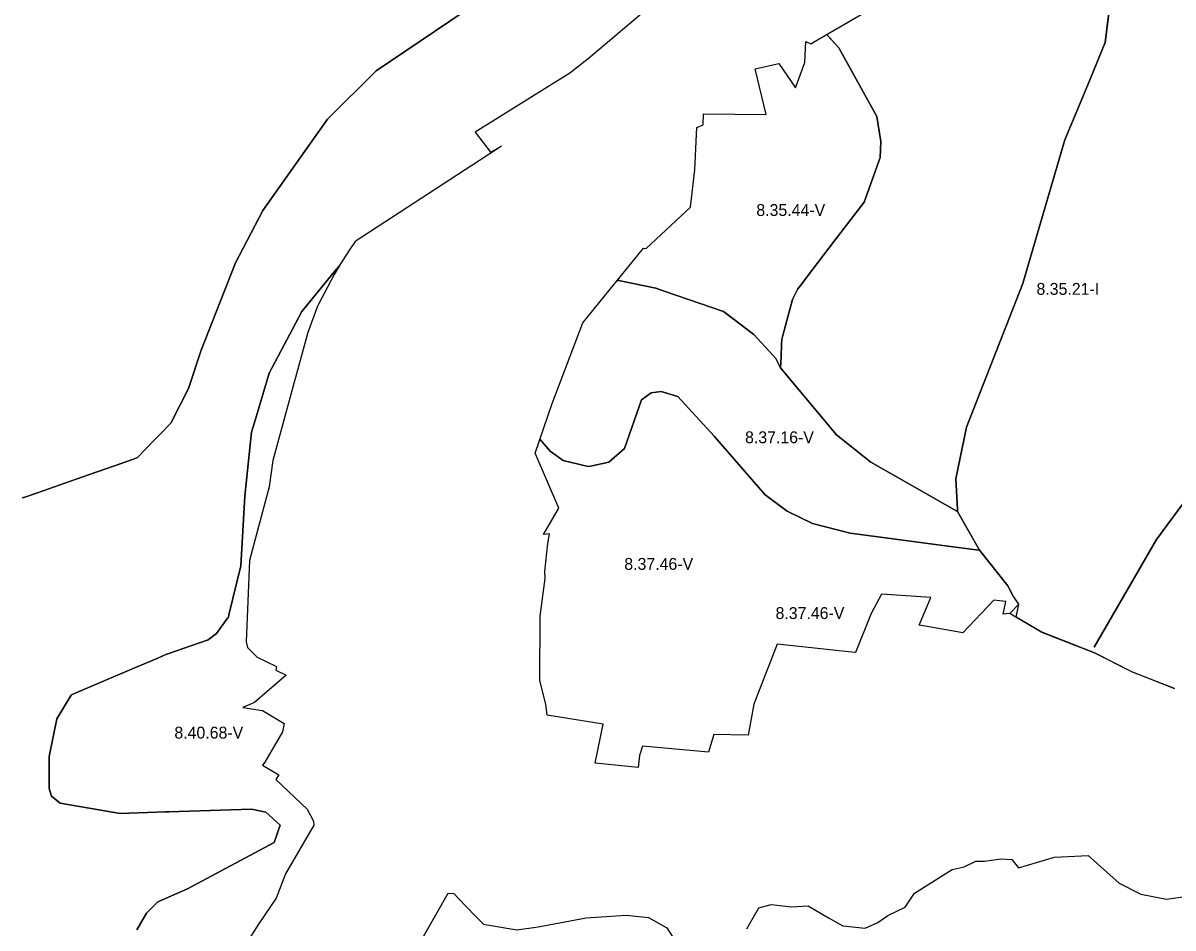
# Model space of a CAD drawing. Extents: x -547623 to -533936, y -1096714 to -1086523.
# Drawn here: x -543752 to -542784, y -1094794 to -1094032 of the extents above; entities that cross this region are included whole.
import ezdxf

# ---------------------------------------------------------------- set-up
doc = ezdxf.new("R2010")
doc.units = 0
doc.layers.add('Vrstva 27', color=7, linetype='Continuous')
doc.layers.add('Vrstva 28', color=7, linetype='Continuous')

msp = doc.modelspace()

# ---------------------------------------------------------------- linework, layer by layer
at = {"layer": 'Vrstva 28'}
for p, q in [((-542841, -1094048.5), (-542835.12, -1094000)), ((-542835.12, -1094000), (-542841, -1094048.5)), ((-543381, -1094022.5), (-543455, -1094072.5)), ((-543455, -1094072.5), (-543381, -1094022.5)), ((-543065.5, -1094053), (-543075.52, -1094041.89)), ((-543075.52, -1094041.89), (-543065.5, -1094053)), ((-542855.78, -1094084.15), (-542841, -1094048.5)), ((-542841, -1094048.5), (-542855.78, -1094084.15)), ((-543033.5, -1094111), (-543065.5, -1094053)), ((-543065.5, -1094053), (-543033.5, -1094111)), ((-543455, -1094072.5), (-543496, -1094113)), ((-543496, -1094113), (-543455, -1094072.5)), ((-542875, -1094130.5), (-542855.78, -1094084.15)), ((-542855.78, -1094084.15), (-542875, -1094130.5)), ((-543030, -1094132), (-543033.5, -1094111)), ((-543033.5, -1094111), (-543030, -1094132)), ((-543496, -1094113), (-543550.5, -1094190)), ((-543550.5, -1094190), (-543496, -1094113)), ((-543030.5, -1094145.5), (-543030, -1094132)), ((-543030, -1094132), (-543030.5, -1094145.5)), ((-542900.06, -1094215.92), (-542875, -1094130.5)), ((-542875, -1094130.5), (-542900.06, -1094215.92)), ((-543044, -1094183), (-543030.5, -1094145.5)), ((-543030.5, -1094145.5), (-543044, -1094183)), ((-543411.41, -1094176.18), (-543411.41, -1094176.18)), ((-543069.25, -1094215.92), (-543044, -1094183)), ((-543044, -1094183), (-543069.25, -1094215.92)), ((-543550.5, -1094190), (-543564.05, -1094215.92)), ((-543564.05, -1094215.92), (-543550.5, -1094190)), ((-543564.05, -1094215.92), (-543573.5, -1094234)), ((-543573.5, -1094234), (-543564.05, -1094215.92)), ((-543091.79, -1094245.3), (-543069.25, -1094215.92)), ((-543069.25, -1094215.92), (-543091.79, -1094245.3)), ((-542910.5, -1094251.5), (-542900.06, -1094215.92)), ((-542900.06, -1094215.92), (-542910.5, -1094251.5)), ((-543573.5, -1094234), (-543602.5, -1094307.5)), ((-543602.5, -1094307.5), (-543573.5, -1094234)), ((-543486.31, -1094236.92), (-543490.45, -1094243.92)), ((-543490.45, -1094243.92), (-543486.31, -1094236.92)), ((-543486.31, -1094236.92), (-543490, -1094241.5)), ((-543490, -1094241.5), (-543486.31, -1094236.92)), ((-543486.31, -1094236.92), (-543486.31, -1094236.92)), ((-543486.31, -1094236.92), (-543486.31, -1094236.92)), ((-543490, -1094241.5), (-543517.5, -1094275)), ((-543517.5, -1094275), (-543490, -1094241.5)), ((-543097.54, -1094252.8), (-543091.79, -1094245.3)), ((-543091.79, -1094245.3), (-543097.54, -1094252.8)), ((-543251, -1094249), (-543252, -1094248.95)), ((-543252, -1094248.95), (-543251, -1094249)), ((-543219.5, -1094255.5), (-543251, -1094249)), ((-543251, -1094249), (-543219.5, -1094255.5)), ((-543211.76, -1094258.15), (-543219.5, -1094255.5)), ((-543219.5, -1094255.5), (-543211.76, -1094258.15)), ((-543104.5, -1094265), (-543100, -1094256)), ((-543100, -1094256), (-543104.5, -1094265)), ((-543100, -1094256), (-543097.54, -1094252.8)), ((-543097.54, -1094252.8), (-543100, -1094256)), ((-542958, -1094372.5), (-542910.5, -1094251.5)), ((-542910.5, -1094251.5), (-542958, -1094372.5)), ((-543162.5, -1094275), (-543211.76, -1094258.15)), ((-543211.76, -1094258.15), (-543162.5, -1094275)), ((-543112.33, -1094294.16), (-543104.5, -1094265)), ((-543104.5, -1094265), (-543112.33, -1094294.16)), ((-543517.5, -1094275), (-543545, -1094327)), ((-543545, -1094327), (-543517.5, -1094275)), ((-543137, -1094294.5), (-543162.5, -1094275)), ((-543162.5, -1094275), (-543137, -1094294.5)), ((-543121.05, -1094311.74), (-543137, -1094294.5)), ((-543137, -1094294.5), (-543121.05, -1094311.74)), ((-543113.5, -1094298.5), (-543112.33, -1094294.16)), ((-543112.33, -1094294.16), (-543113.5, -1094298.5)), ((-543114.11, -1094313.07), (-543113.66, -1094302.45)), ((-543113.66, -1094302.45), (-543114.11, -1094313.07)), ((-543113.66, -1094302.45), (-543113.5, -1094298.5)), ((-543113.5, -1094298.5), (-543113.66, -1094302.45)), ((-543602.5, -1094307.5), (-543613, -1094340)), ((-543613, -1094340), (-543602.5, -1094307.5)), ((-543118.5, -1094314.5), (-543121.05, -1094311.74)), ((-543121.05, -1094311.74), (-543118.5, -1094314.5)), ((-543114.5, -1094322.5), (-543114.11, -1094313.07)), ((-543114.11, -1094313.07), (-543114.5, -1094322.5)), ((-543117.94, -1094315.62), (-543118.5, -1094314.5)), ((-543118.5, -1094314.5), (-543117.94, -1094315.62)), ((-543116.13, -1094319.23), (-543117.94, -1094315.62)), ((-543117.94, -1094315.62), (-543116.13, -1094319.23)), ((-543114.5, -1094322.5), (-543116.13, -1094319.23)), ((-543116.13, -1094319.23), (-543114.5, -1094322.5)), ((-543067.5, -1094379), (-543114.5, -1094322.5)), ((-543114.5, -1094322.5), (-543067.5, -1094379)), ((-543545, -1094327), (-543555.87, -1094362.88)), ((-543555.87, -1094362.88), (-543545, -1094327)), ((-543613, -1094340), (-543628, -1094369)), ((-543628, -1094369), (-543613, -1094340)), ((-543215, -1094342.5), (-543223.5, -1094343.5)), ((-543223.5, -1094343.5), (-543215, -1094342.5)), ((-543201, -1094346.5), (-543215, -1094342.5)), ((-543215, -1094342.5), (-543201, -1094346.5)), ((-543231.5, -1094349.5), (-543246, -1094390.5)), ((-543246, -1094390.5), (-543231.5, -1094349.5)), ((-543223.5, -1094343.5), (-543231.5, -1094349.5)), ((-543231.5, -1094349.5), (-543223.5, -1094343.5)), ((-543170.5, -1094380), (-543201, -1094346.5)), ((-543201, -1094346.5), (-543170.5, -1094380)), ((-543628, -1094369), (-543637.14, -1094378.47)), ((-543637.14, -1094378.47), (-543628, -1094369)), ((-543555.87, -1094362.88), (-543560, -1094376.5)), ((-543560, -1094376.5), (-543555.87, -1094362.88)), ((-542967, -1094416), (-542958, -1094372.5)), ((-542958, -1094372.5), (-542967, -1094416)), ((-543637.14, -1094378.47), (-543641.17, -1094382.64)), ((-543641.17, -1094382.64), (-543637.14, -1094378.47)), ((-543560, -1094376.5), (-543565.5, -1094430.5)), ((-543565.5, -1094430.5), (-543560, -1094376.5)), ((-543127.5, -1094429.5), (-543170.5, -1094380)), ((-543170.5, -1094380), (-543127.5, -1094429.5)), ((-543038.5, -1094402), (-543067.5, -1094379)), ((-543067.5, -1094379), (-543038.5, -1094402)), ((-543641.17, -1094382.64), (-543656, -1094398)), ((-543656, -1094398), (-543641.17, -1094382.64)), ((-543308.5, -1094392.5), (-543317.14, -1094382.59)), ((-543317.14, -1094382.59), (-543308.5, -1094392.5)), ((-543246, -1094390.5), (-543259, -1094402)), ((-543259, -1094402), (-543246, -1094390.5)), ((-543659.46, -1094399.21), (-543681.88, -1094407.09)), ((-543681.88, -1094407.09), (-543659.46, -1094399.21)), ((-543656, -1094398), (-543659.46, -1094399.21)), ((-543659.46, -1094399.21), (-543656, -1094398)), ((-543297.5, -1094400.5), (-543308.5, -1094392.5)), ((-543308.5, -1094392.5), (-543297.5, -1094400.5)), ((-543276.5, -1094405.5), (-543297.5, -1094400.5)), ((-543297.5, -1094400.5), (-543276.5, -1094405.5)), ((-543691.68, -1094410.53), (-543707.72, -1094416.17)), ((-543707.72, -1094416.17), (-543691.68, -1094410.53)), ((-543689.09, -1094409.62), (-543691.68, -1094410.53)), ((-543691.68, -1094410.53), (-543689.09, -1094409.62)), ((-543681.88, -1094407.09), (-543689.09, -1094409.62)), ((-543689.09, -1094409.62), (-543681.88, -1094407.09)), ((-543274.61, -1094405.12), (-543276.5, -1094405.5)), ((-543276.5, -1094405.5), (-543274.61, -1094405.12)), ((-543259, -1094402), (-543274.61, -1094405.12)), ((-543274.61, -1094405.12), (-543259, -1094402)), ((-543004, -1094421.61), (-543038.5, -1094402)), ((-543038.5, -1094402), (-543004, -1094421.61)), ((-543707.72, -1094416.17), (-543741.12, -1094427.9)), ((-543741.12, -1094427.9), (-543707.72, -1094416.17)), ((-542965.59, -1094441.75), (-542967, -1094416)), ((-542967, -1094416), (-542965.59, -1094441.75)), ((-543741.12, -1094427.9), (-543750, -1094431.02)), ((-543750, -1094431.02), (-543741.12, -1094427.9)), ((-543565.5, -1094430.5), (-543569, -1094489)), ((-543569, -1094489), (-543565.5, -1094430.5)), ((-543109, -1094443), (-543127.5, -1094429.5)), ((-543127.5, -1094429.5), (-543109, -1094443)), ((-542965.98, -1094443.23), (-543004, -1094421.61)), ((-543004, -1094421.61), (-542965.98, -1094443.23)), ((-542770, -1094429.5), (-542798, -1094467)), ((-542798, -1094467), (-542770, -1094429.5)), ((-543750, -1094431.02), (-543752.84, -1094432.02)), ((-543752.84, -1094432.02), (-543750, -1094431.02)), ((-543087.5, -1094453.5), (-543109, -1094443)), ((-543109, -1094443), (-543087.5, -1094453.5)), ((-542965.5, -1094443.5), (-542965.98, -1094443.23)), ((-542965.98, -1094443.23), (-542965.5, -1094443.5)), ((-542965.5, -1094443.5), (-542965.59, -1094441.75)), ((-542965.59, -1094441.75), (-542965.5, -1094443.5)), ((-542947, -1094476), (-542965.5, -1094443.5)), ((-542965.5, -1094443.5), (-542947, -1094476)), ((-543056, -1094461.5), (-543087.5, -1094453.5)), ((-543087.5, -1094453.5), (-543056, -1094461.5)), ((-543017.68, -1094466.6), (-543056, -1094461.5)), ((-543056, -1094461.5), (-543017.68, -1094466.6)), ((-542973.54, -1094472.47), (-543017.68, -1094466.6)), ((-543017.68, -1094466.6), (-542973.54, -1094472.47)), ((-542798, -1094467), (-542850.5, -1094557.5)), ((-542850.5, -1094557.5), (-542798, -1094467)), ((-542951.91, -1094475.35), (-542973.54, -1094472.47)), ((-542973.54, -1094472.47), (-542951.91, -1094475.35)), ((-542947, -1094476), (-542951.91, -1094475.35)), ((-542951.91, -1094475.35), (-542947, -1094476)), ((-542923, -1094506), (-542947, -1094476)), ((-542947, -1094476), (-542923, -1094506)), ((-543569, -1094489), (-543579, -1094530.43)), ((-543579, -1094530.43), (-543569, -1094489)), ((-542922.19, -1094507.61), (-542923, -1094506)), ((-542923, -1094506), (-542922.19, -1094507.61)), ((-542919, -1094514), (-542922.19, -1094507.61)), ((-542922.19, -1094507.61), (-542919, -1094514)), ((-542913.77, -1094521.49), (-542919, -1094514)), ((-543580.11, -1094533.33), (-543589.5, -1094546)), ((-543589.5, -1094546), (-543580.11, -1094533.33)), ((-543579.5, -1094532.5), (-543580.11, -1094533.33)), ((-543580.11, -1094533.33), (-543579.5, -1094532.5)), ((-543579, -1094530.43), (-543579.5, -1094532.5)), ((-543579.5, -1094532.5), (-543579, -1094530.43)), ((-543589.5, -1094546), (-543596.5, -1094551.5)), ((-543596.5, -1094551.5), (-543589.5, -1094546)), ((-543611.07, -1094556.5), (-543624.02, -1094560.94)), ((-543624.02, -1094560.94), (-543611.07, -1094556.5)), ((-543596.5, -1094551.5), (-543611.07, -1094556.5)), ((-543611.07, -1094556.5), (-543596.5, -1094551.5)), ((-543635.29, -1094565.12), (-543639.03, -1094566.73)), ((-543639.03, -1094566.73), (-543635.29, -1094565.12)), ((-543631.5, -1094563.5), (-543635.29, -1094565.12)), ((-543635.29, -1094565.12), (-543631.5, -1094563.5)), ((-543629.46, -1094562.8), (-543631.5, -1094563.5)), ((-543631.5, -1094563.5), (-543629.46, -1094562.8)), ((-543628.71, -1094562.54), (-543629.46, -1094562.8)), ((-543629.46, -1094562.8), (-543628.71, -1094562.54)), ((-543624.02, -1094560.94), (-543628.71, -1094562.54)), ((-543628.71, -1094562.54), (-543624.02, -1094560.94)), ((-543659.22, -1094575.38), (-543709.01, -1094596.72)), ((-543709.01, -1094596.72), (-543659.22, -1094575.38)), ((-543657.62, -1094574.69), (-543659.22, -1094575.38)), ((-543659.22, -1094575.38), (-543657.62, -1094574.69)), ((-543639.03, -1094566.73), (-543657.62, -1094574.69)), ((-543657.62, -1094574.69), (-543639.03, -1094566.73)), ((-543712, -1094598), (-543724, -1094618)), ((-543724, -1094618), (-543712, -1094598)), ((-543711.62, -1094597.84), (-543712, -1094598)), ((-543712, -1094598), (-543711.62, -1094597.84)), ((-543709.01, -1094596.72), (-543711.62, -1094597.84)), ((-543711.62, -1094597.84), (-543709.01, -1094596.72)), ((-543724, -1094618), (-543730.5, -1094649.5)), ((-543730.5, -1094649.5), (-543724, -1094618)), ((-543730.5, -1094649.5), (-543730.5, -1094676.5)), ((-543730.5, -1094676.5), (-543730.5, -1094649.5)), ((-543730.5, -1094676.5), (-543728.5, -1094683)), ((-543728.5, -1094683), (-543730.5, -1094676.5)), ((-543728.5, -1094683), (-543721, -1094689)), ((-543721, -1094689), (-543728.5, -1094683)), ((-543721, -1094689), (-543670.5, -1094697.5)), ((-543670.5, -1094697.5), (-543721, -1094689)), ((-543670.5, -1094697.5), (-543632.4, -1094696.29)), ((-543632.4, -1094696.29), (-543670.5, -1094697.5)), ((-543632.4, -1094696.29), (-543629.56, -1094696.2)), ((-543629.56, -1094696.2), (-543632.4, -1094696.29)), ((-543629.56, -1094696.2), (-543560, -1094694)), ((-543560, -1094694), (-543629.56, -1094696.2)), ((-543560, -1094694), (-543548, -1094696.5)), ((-543548, -1094696.5), (-543560, -1094694)), ((-543548, -1094696.5), (-543536, -1094707.5)), ((-543536, -1094707.5), (-543548, -1094696.5)), ((-543536, -1094707.5), (-543541, -1094722)), ((-543541, -1094722), (-543536, -1094707.5)), ((-543541, -1094722), (-543614, -1094761)), ((-543614, -1094761), (-543541, -1094722)), ((-543614, -1094761), (-543639, -1094772)), ((-543639, -1094772), (-543614, -1094761)), ((-543639, -1094772), (-543648.5, -1094781.5)), ((-543648.5, -1094781.5), (-543639, -1094772)), ((-543648.5, -1094781.5), (-543656.5, -1094795.5)), ((-543656.5, -1094795.5), (-543648.5, -1094781.5))]:
    msp.add_line(p, q, dxfattribs=at)
for points in [[(-543074.89, -1094042.58), (-543065.5, -1094053), (-543033.5, -1094111), (-543030, -1094132), (-543030.5, -1094145.5), (-543044, -1094183), (-543069.25, -1094215.92), (-543091.79, -1094245.3), (-543097.54, -1094252.8), (-543100, -1094256), (-543104.5, -1094265), (-543112.33, -1094294.16), (-543113.5, -1094298.5), (-543113.66, -1094302.45), (-543114.11, -1094313.07), (-543114.5, -1094322.5), (-543067.5, -1094379), (-543038.5, -1094402), (-543004, -1094421.61), (-542965.98, -1094443.23), (-542965.5, -1094443.5), (-542965.59, -1094441.75), (-542967, -1094416), (-542958, -1094372.5), (-542910.5, -1094251.5), (-542900.06, -1094215.92), (-542875, -1094130.5), (-542855.78, -1094084.15), (-542841, -1094048.5), (-542835.12, -1094000)], [(-543381, -1094022.5), (-543455, -1094072.5), (-543496, -1094113), (-543550.5, -1094190), (-543564.05, -1094215.92), (-543573.5, -1094234), (-543602.5, -1094307.5), (-543613, -1094340), (-543628, -1094369), (-543637.14, -1094378.47), (-543641.17, -1094382.64), (-543656, -1094398), (-543659.46, -1094399.21), (-543681.88, -1094407.09), (-543689.09, -1094409.62), (-543691.68, -1094410.53), (-543707.72, -1094416.17), (-543741.12, -1094427.9), (-543750, -1094431.02), (-543752.84, -1094432.02)], [(-543752.84, -1094432.02), (-543750, -1094431.02), (-543741.12, -1094427.9), (-543707.72, -1094416.17), (-543691.68, -1094410.53), (-543689.09, -1094409.62), (-543681.88, -1094407.09), (-543659.46, -1094399.21), (-543656, -1094398), (-543641.17, -1094382.64), (-543637.14, -1094378.47), (-543628, -1094369), (-543613, -1094340), (-543602.5, -1094307.5), (-543573.5, -1094234), (-543564.05, -1094215.92), (-543550.5, -1094190), (-543496, -1094113), (-543455, -1094072.5), (-543381, -1094022.5)], [(-543220.59, -1094015.21), (-543276.45, -1094062.24), (-543291.88, -1094074.5), (-543371.53, -1094124.21), (-543358.82, -1094140.86), (-543349.43, -1094135.79), (-543472.68, -1094216.11), (-543477.52, -1094223.26), (-543485.6, -1094235.73), (-543490.45, -1094243.92), (-543504.47, -1094270.65), (-543512.7, -1094292.85), (-543525.1, -1094338.86), (-543533.57, -1094369.47), (-543542.17, -1094400.54), (-543545.02, -1094422.5), (-543561.78, -1094484.59), (-543564.5, -1094553.01), (-543563.51, -1094557.92), (-543555.37, -1094566.06), (-543538.98, -1094573.93), (-543539.59, -1094576.96), (-543530.77, -1094581.21), (-543546.98, -1094595.16), (-543557.47, -1094604.09), (-543567.21, -1094608.39), (-543550.79, -1094610.92), (-543532.58, -1094621.73), (-543534, -1094629), (-543548.87, -1094654.28), (-543550.8, -1094656.86), (-543536.93, -1094665.04), (-543539.55, -1094669.09), (-543513.17, -1094693.85), (-543507.84, -1094703.94), (-543507.61, -1094707.54), (-543531.48, -1094748.33), (-543539.12, -1094768.8), (-543554.15, -1094790.67), (-543577.79, -1094827.76)], [(-542782.48, -1094592.63), (-542818.56, -1094578.48), (-542849.7, -1094562.72), (-542894.53, -1094545.14), (-542916.43, -1094532.22), (-542921.32, -1094529.14), (-542926.93, -1094529.76), (-542924.67, -1094519.18), (-542934.77, -1094518.04), (-542961.01, -1094545.56), (-542992.67, -1094539.91), (-542997.63, -1094538.98), (-542987.81, -1094515.77), (-543029.51, -1094512.88), (-543038.18, -1094529.37), (-543051.5, -1094562.03), (-543052.03, -1094561.99), (-543117.27, -1094554.97), (-543137.01, -1094605.48), (-543141.79, -1094631.69), (-543170.54, -1094631.14), (-543175.17, -1094646.12), (-543230.76, -1094641.07), (-543233.38, -1094648.69), (-543234.34, -1094659.03), (-543270.62, -1094655.31), (-543263.84, -1094622.41), (-543310.9, -1094614.76), (-543312.28, -1094605.52), (-543317.15, -1094585.68), (-543317.01, -1094531.39), (-543312.61, -1094499.84), (-543313.12, -1094493.8), (-543310.42, -1094470.41), (-543309.11, -1094462.27), (-543314.18, -1094462.67), (-543301.34, -1094440.73), (-543321.13, -1094394.35), (-543306.92, -1094352.42), (-543280.94, -1094284.68), (-543229.84, -1094221.6), (-543227.55, -1094222.12), (-543190.32, -1094187.29), (-543186.81, -1094155.76), (-543184.94, -1094120.23), (-543179.76, -1094117.95), (-543179.49, -1094108.61), (-543126.5, -1094109.2), (-543135.87, -1094070.67), (-543116.06, -1094066.36), (-543101.77, -1094086.85), (-543093.96, -1094065.51), (-543093.1, -1094047.83), (-543089.09, -1094049.85), (-543086.68, -1094048.41), (-543036.39, -1094019.02)], [(-543211.76, -1094258.15), (-543162.5, -1094275), (-543137, -1094294.5), (-543121.05, -1094311.74), (-543118.5, -1094314.5), (-543117.94, -1094315.62), (-543116.13, -1094319.23), (-543114.5, -1094322.5), (-543114.11, -1094313.07), (-543113.66, -1094302.45), (-543113.5, -1094298.5), (-543112.33, -1094294.16), (-543104.5, -1094265), (-543100, -1094256), (-543097.54, -1094252.8), (-543091.79, -1094245.3), (-543069.25, -1094215.92), (-543044, -1094183), (-543030.5, -1094145.5), (-543030, -1094132), (-543033.5, -1094111), (-543065.5, -1094053), (-543075.51, -1094041.89)], [(-542782.74, -1094592.44), (-542818.18, -1094578.59), (-542850.15, -1094562.5), (-542894.93, -1094544.81), (-542916.2, -1094532.21), (-542913.77, -1094521.49), (-542921.32, -1094529.14), (-542926.93, -1094529.76), (-542924.67, -1094519.18), (-542934.77, -1094518.04), (-542961.01, -1094545.56), (-542992.67, -1094539.91), (-542997.63, -1094538.98), (-542987.81, -1094515.77), (-543029.51, -1094512.88), (-543038.18, -1094529.37), (-543051.5, -1094562.03), (-543052.03, -1094561.99), (-543117.27, -1094554.97), (-543137.01, -1094605.48), (-543141.79, -1094631.69), (-543170.54, -1094631.14), (-543175.17, -1094646.12), (-543230.76, -1094641.07), (-543233.38, -1094648.69), (-543234.34, -1094659.03), (-543270.62, -1094655.31), (-543263.84, -1094622.41), (-543310.9, -1094614.76), (-543312.28, -1094605.52), (-543317.15, -1094585.68), (-543317.01, -1094531.39), (-543312.61, -1094499.84), (-543313.12, -1094493.8), (-543310.42, -1094470.41), (-543309.11, -1094462.27), (-543314.18, -1094462.67), (-543301.34, -1094440.73), (-543321.13, -1094394.35), (-543306.92, -1094352.42), (-543280.94, -1094284.68), (-543229.84, -1094221.6), (-543227.55, -1094222.12), (-543190.32, -1094187.29), (-543186.81, -1094155.76), (-543184.94, -1094120.23), (-543179.76, -1094117.95), (-543179.49, -1094108.61), (-543126.5, -1094109.2), (-543135.87, -1094070.67), (-543116.06, -1094066.36), (-543101.77, -1094086.85), (-543093.96, -1094065.51), (-543093.1, -1094047.83), (-543089.09, -1094049.85)], [(-543656.5, -1094795.5), (-543648.5, -1094781.5), (-543639, -1094772), (-543614, -1094761), (-543541, -1094722), (-543536, -1094707.5), (-543548, -1094696.5), (-543560, -1094694), (-543629.56, -1094696.2), (-543632.4, -1094696.29), (-543670.5, -1094697.5), (-543721, -1094689), (-543728.5, -1094683), (-543730.5, -1094676.5), (-543730.5, -1094649.5), (-543724, -1094618), (-543712, -1094598), (-543711.62, -1094597.84), (-543709.01, -1094596.72), (-543659.22, -1094575.38), (-543657.62, -1094574.69), (-543639.03, -1094566.73), (-543635.29, -1094565.12), (-543631.5, -1094563.5), (-543629.46, -1094562.8), (-543628.71, -1094562.54), (-543624.02, -1094560.94), (-543611.07, -1094556.5), (-543596.5, -1094551.5), (-543589.5, -1094546), (-543580.11, -1094533.33), (-543579.5, -1094532.5), (-543579, -1094530.43), (-543569, -1094489), (-543565.5, -1094430.5), (-543560, -1094376.5), (-543555.87, -1094362.88), (-543545, -1094327), (-543517.5, -1094275), (-543490, -1094241.5), (-543486.31, -1094236.92), (-543486.31, -1094236.92)], [(-543250.49, -1094247.09), (-543252, -1094248.95)], [(-543252, -1094248.95), (-543251, -1094249), (-543219.5, -1094255.5), (-543211.76, -1094258.15)], [(-543143.01, -1094794.84), (-543132.67, -1094776.92), (-543122.35, -1094774.18), (-543105.26, -1094776.31), (-543091.27, -1094775.39), (-543074.04, -1094785.52), (-543062.02, -1094792.18), (-543043.18, -1094794.28), (-543032.67, -1094789.25), (-543024.01, -1094783.56), (-543009.57, -1094776.35), (-543001.59, -1094764.68), (-542970.01, -1094744.77), (-542959.82, -1094742.54), (-542950.11, -1094737.71), (-542942.81, -1094737.73), (-542929.09, -1094735.8), (-542919.86, -1094736.34), (-542914.22, -1094743.34), (-542883.92, -1094734.38), (-542855.58, -1094733.11), (-542829.35, -1094756.2), (-542810.98, -1094765.58), (-542789.34, -1094769.79), (-542768.15, -1094766.78)], [(-543441.91, -1094848.09), (-543394.38, -1094764.74), (-543389.49, -1094764.93), (-543385.71, -1094769.21), (-543371.93, -1094783.51), (-543364.7, -1094790.79), (-543358.26, -1094792.04), (-543336.44, -1094795.57), (-543318.63, -1094793.07), (-543278.17, -1094785.43), (-543244.47, -1094783.32), (-543225.67, -1094785.15), (-543210.19, -1094794), (-543203.26, -1094804.71)]]:
    msp.add_lwpolyline(points, dxfattribs=at)

# ---------------------------------------------------------------- texts
at = {"layer": 'Vrstva 27'}
for s, p in [('8.35.44-V', (-543134.88, -1094194.63)), ('8.35.21-I', (-542898.96, -1094261.01)), ('8.37.16-V', (-543144.38, -1094385.93)), ('8.37.46-V', (-543246.07, -1094492.52)), ('8.37.46-V', (-543118.72, -1094533.92)), ('8.40.68-V', (-543624.96, -1094634.56))]:
    msp.add_text(s, height=10, dxfattribs=at).set_placement(p)

doc.saveas('drawing.dxf')
